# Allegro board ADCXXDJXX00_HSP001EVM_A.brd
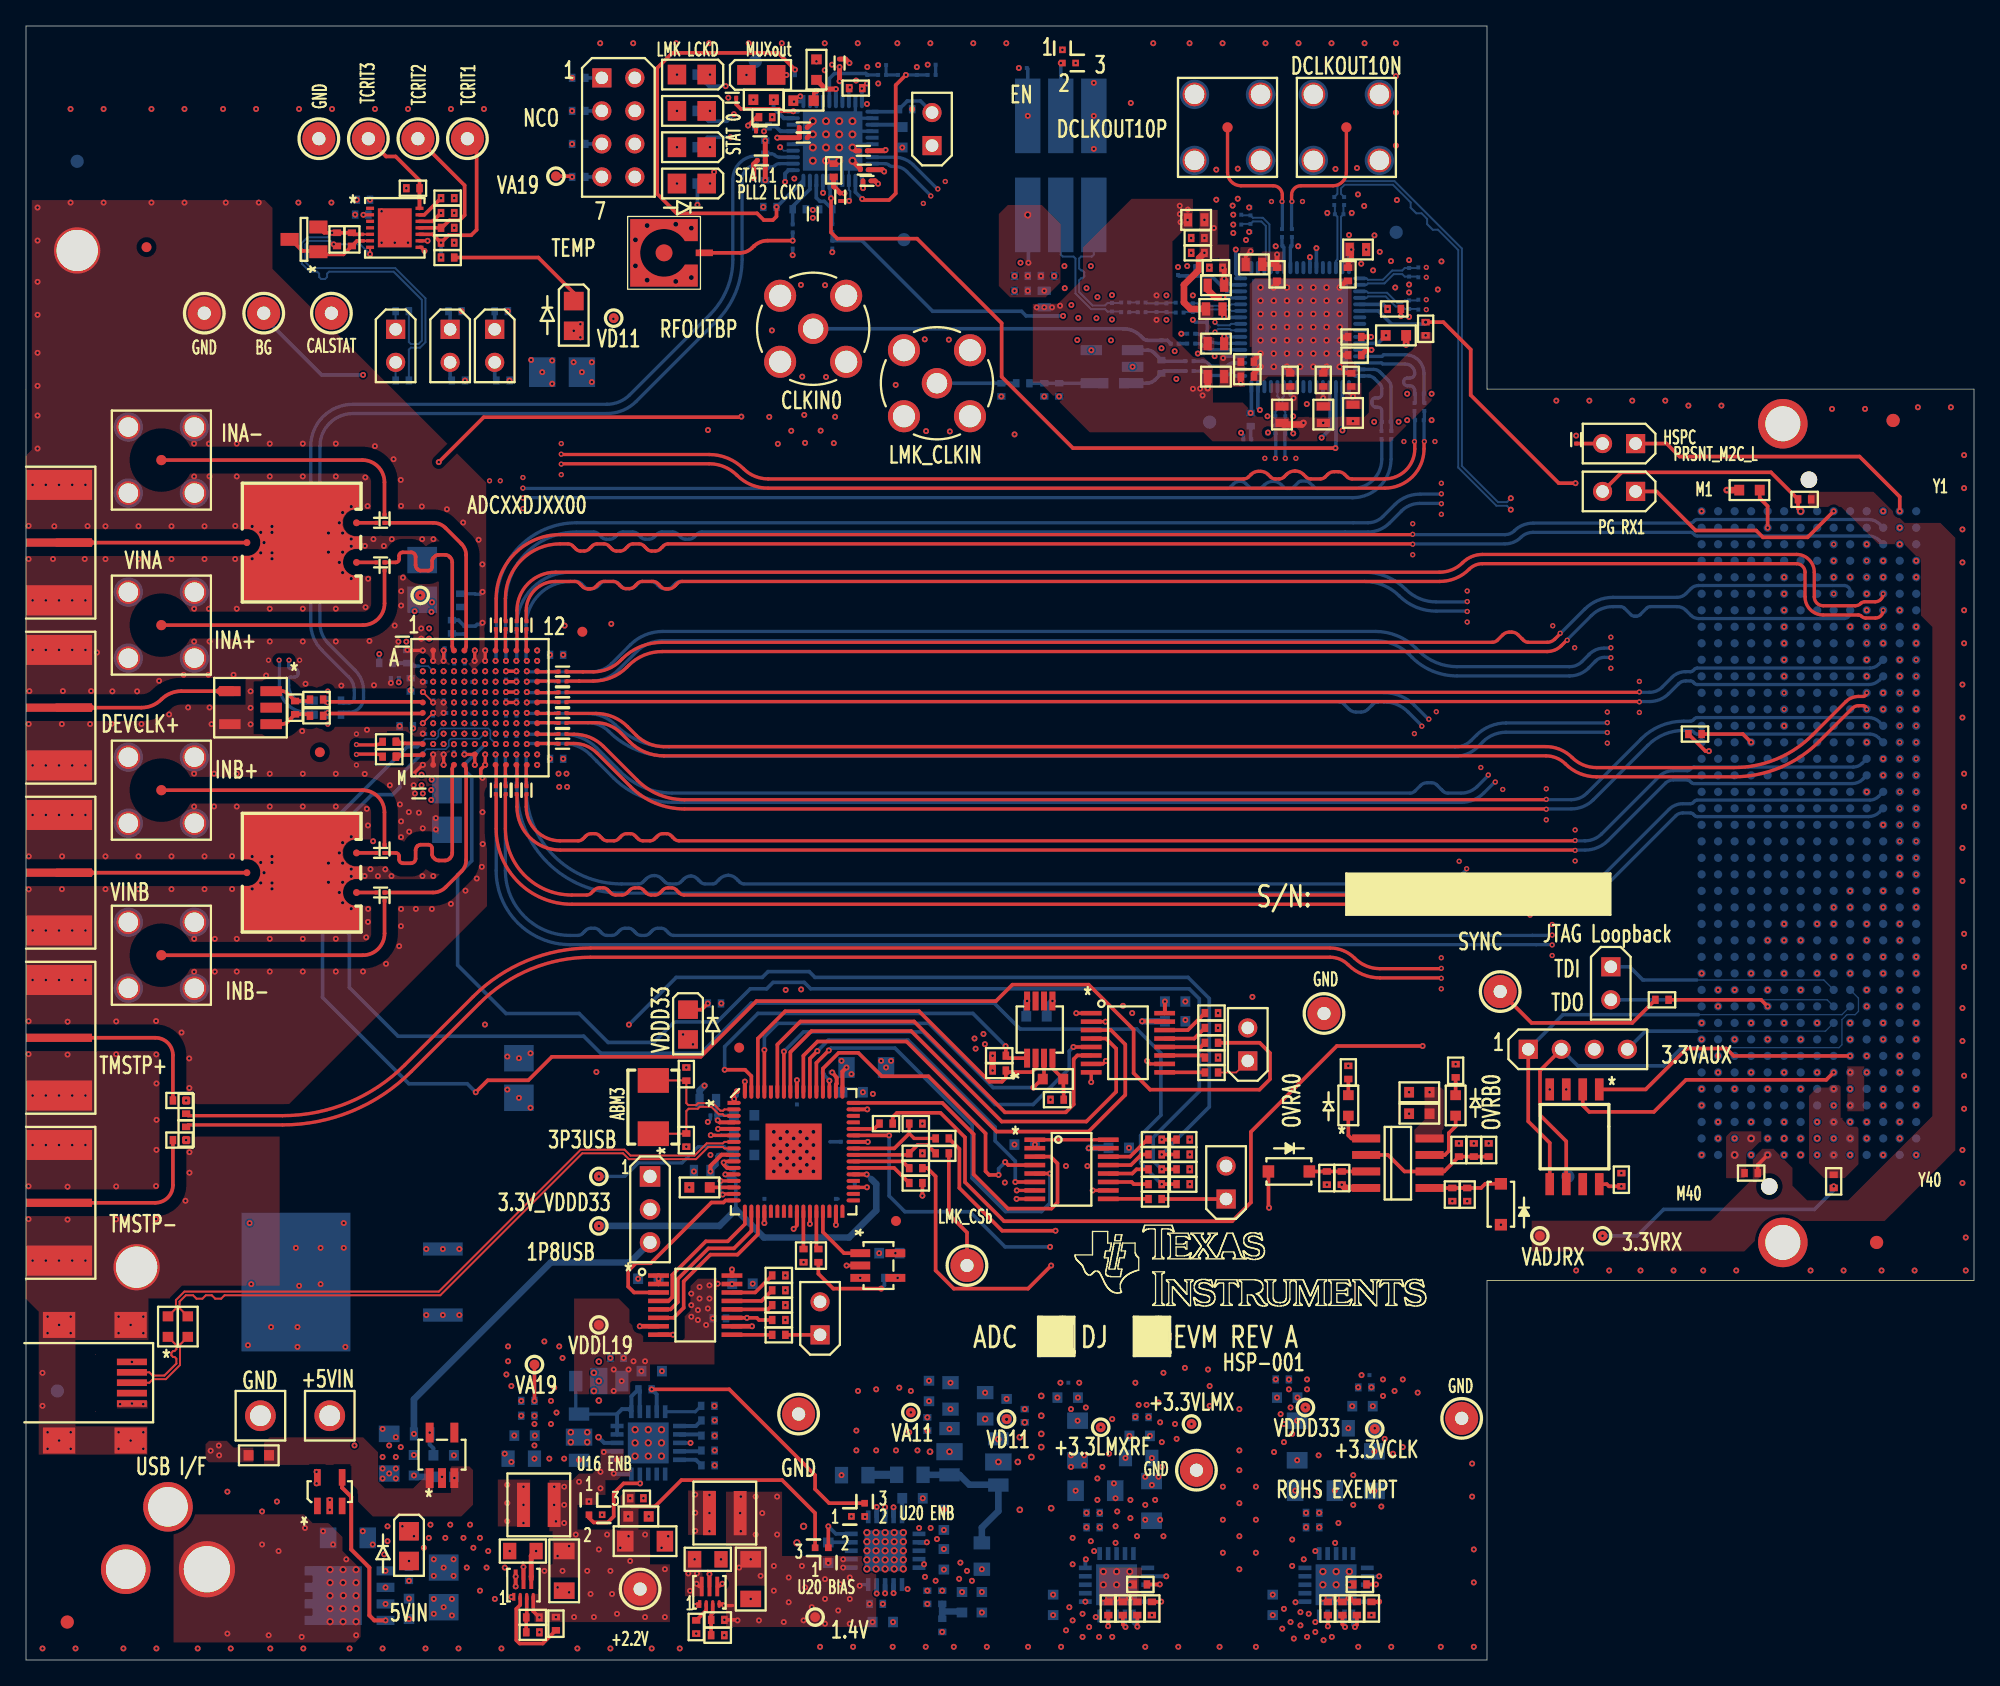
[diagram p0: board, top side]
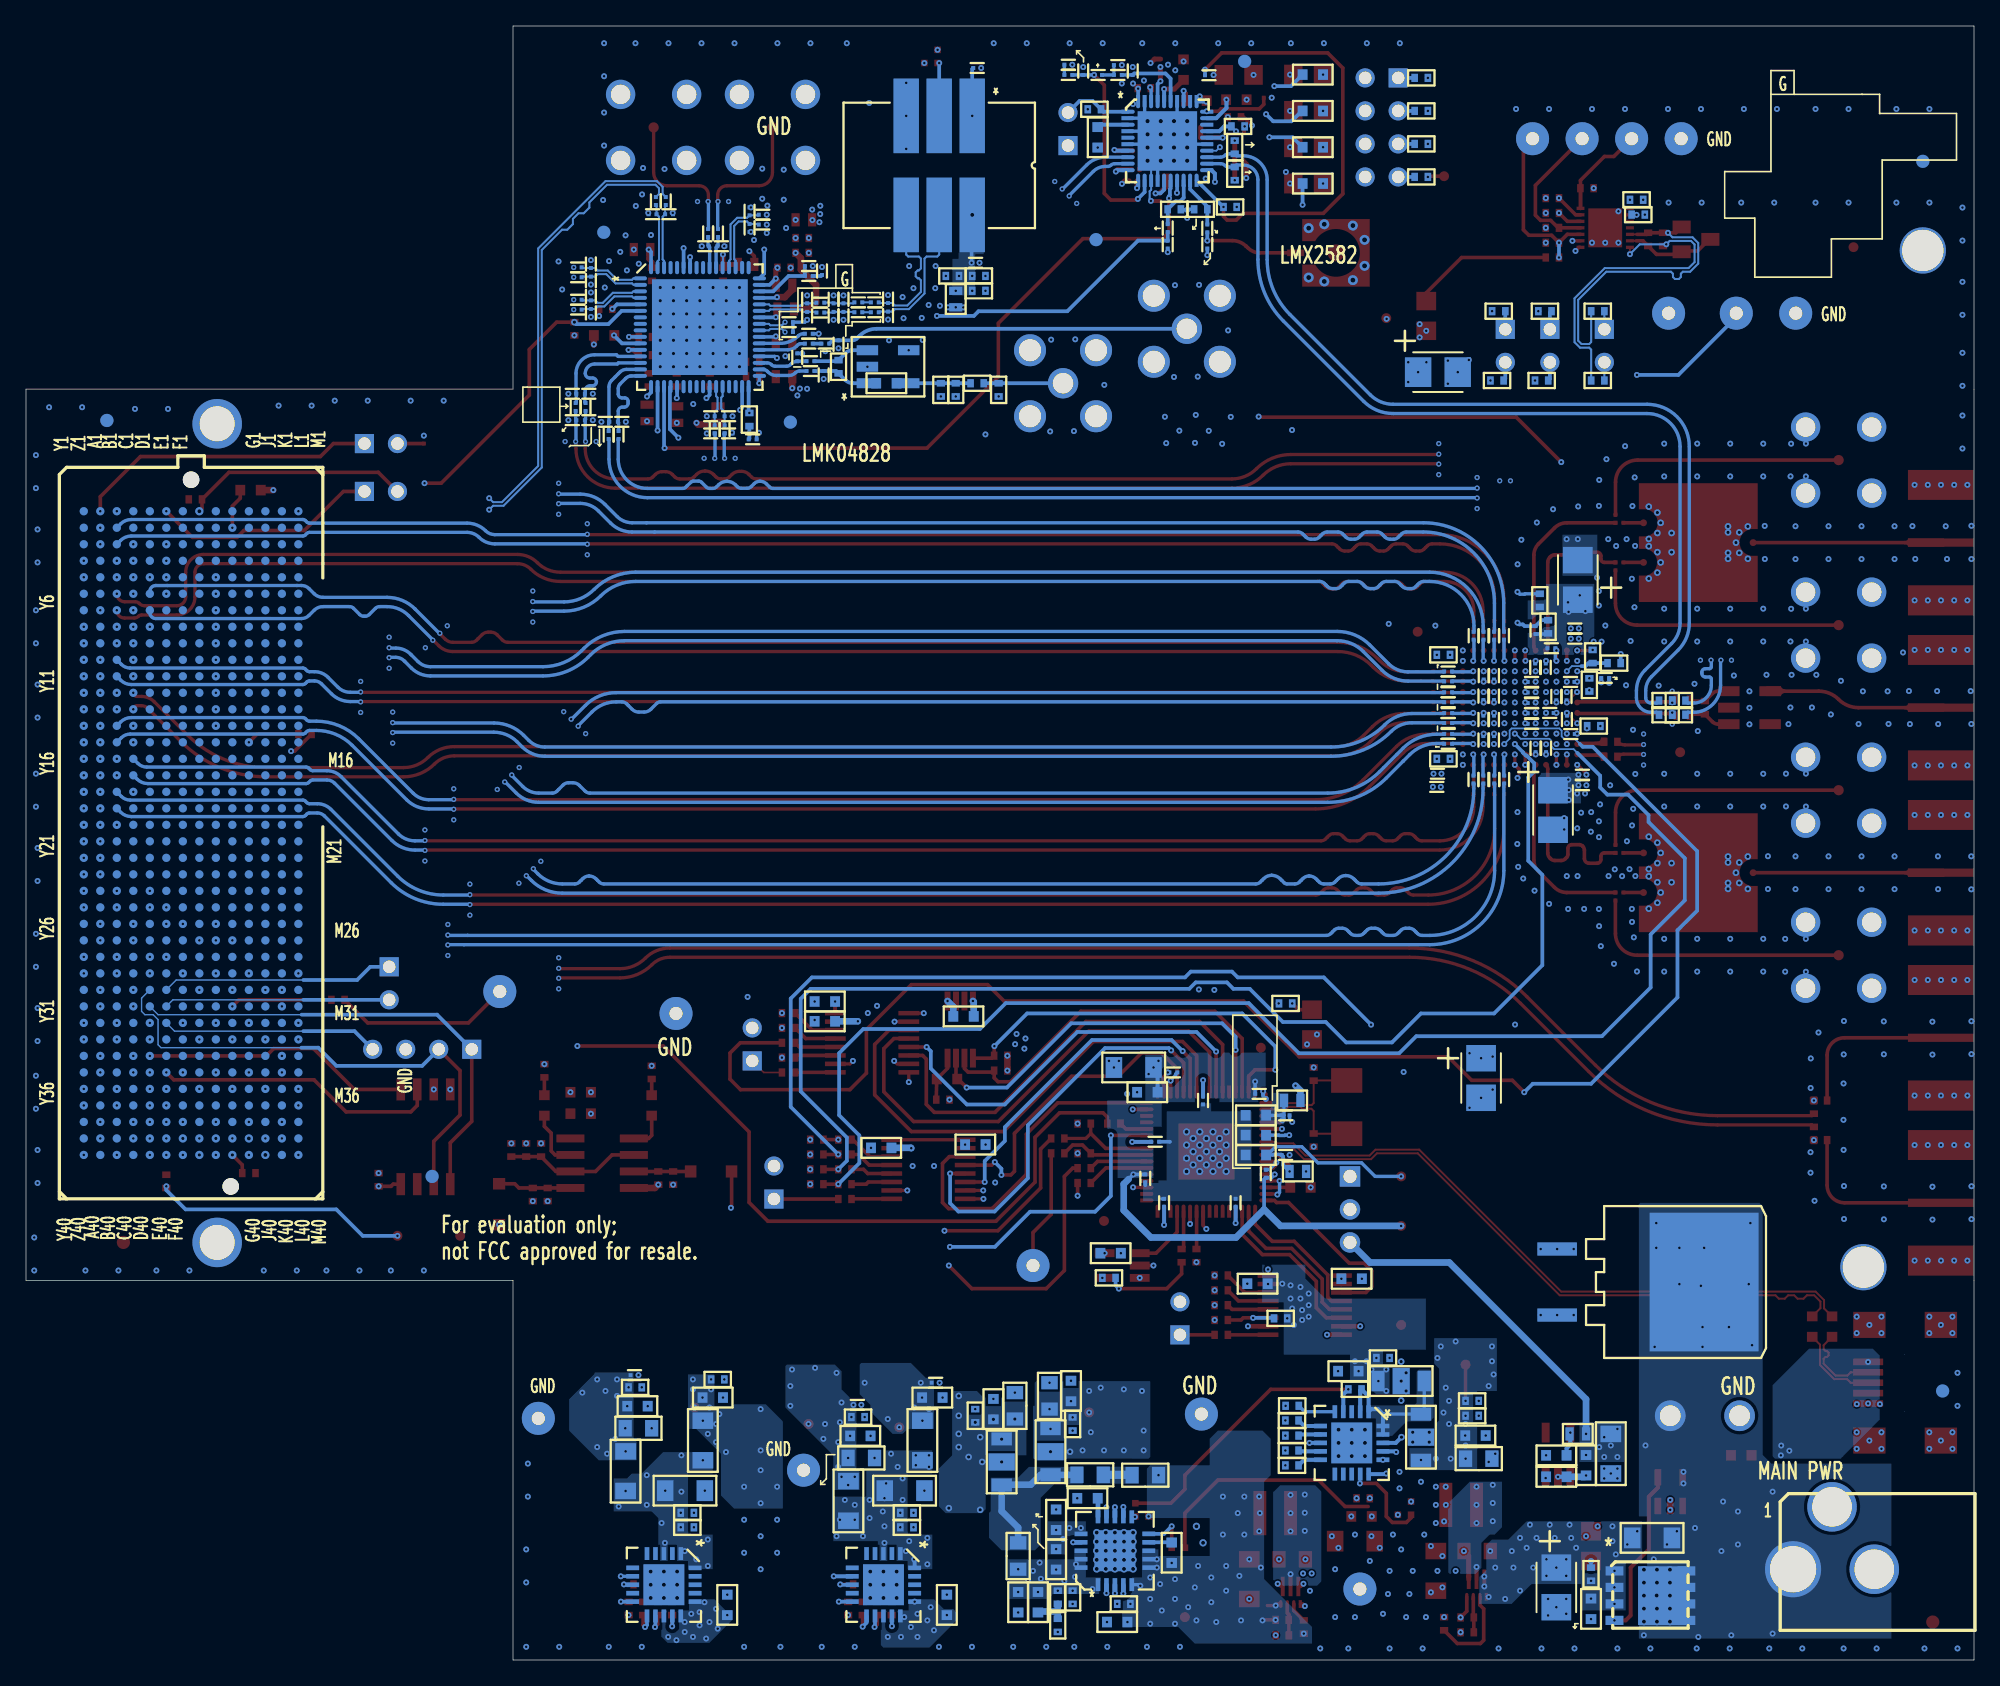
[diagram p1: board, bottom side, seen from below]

Outline 149.86 x 125.73 mm; copper layers: TOP, L02_GND-1, L03_GND-2, L04_SIG-1, L05_GND-3, L06_PWR-1, L07_GND-4, L08_PWR-2, L09_GND-5, L10_SIG-2, L11_GND-6, BOTTOM. Coordinates in mm from the lower left corner of the outline.
Outline path: 0,125.73 0,0 112.39,0 112.39,29.21 149.86,29.21 149.86,97.79 112.39,97.79 112.39,125.73 0,125.73

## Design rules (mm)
net group CLK: nets CLKM CLKP
net group CLKIN0_P_N: nets CLKIN0_N CLKIN0_P
net group CLKIN1: nets CLKIN1_N CLKIN1_P
net group CLKINN: nets CLKINN CLKINP
net group CLKLA0: nets CLKLA_0N CLKLA_0P
net group DA4: nets DA4+ DA4-
net group DA5: nets DA5+ DA5-
net group DA6: nets DA6+ DA6-
net group DA7: nets DA7+ DA7-
net group DB4: nets DB4+ DB4-
net group DB5: nets DB5+ DB5-
net group DB6: nets DB6+ DB6-
net group DB7: nets DB7+ DB7-
net group DCLKOUT2: nets DCLKOUT2_N DCLKOUT2_P
net group DCLKOUT8: nets DCLKOUT8_N DCLKOUT8_P
net group DCLKOUT102: nets DCLKOUT10_N DCLKOUT10_P
net group DIFFPAIR9: nets GTXCLKM GTXCLKP
net group DIFFPAIR10: nets N20382827 N20382847
net group DMP: nets DM DP
net group DP5: nets SYSREF+ SYSREF-
net group DP8: nets LMX_OSCM LMX_OSCP
net group DP17: nets JESD_SYSREFM JESD_SYSREFP
net group DP19: nets LMX_CLKM LMX_CLKP
net group FPGA_JESD_CLKC: nets FPGA_JESD_CLK_C_N FPGA_JESD_CLK_C_P
net group OSC: nets OSCN OSCP
net group OSC_PAIR: nets OSC_M OSC_P
net group OSCIN: nets OSCINN OSCINP
net group OSCIO: nets OSCI OSCO
net group OSCOUT: nets DCLKOUT6_N DCLKOUT6_P
net group SYNC: nets SYNC_N SYNC_P
net group SYSREF: nets SYSREFM SYSREFP
net group TDIODE: nets TDIODE+ TDIODE-
net group TDIODENP: nets TDIODEN TDIODEP
net group TMSTP: nets TMSTP+ TMSTP-
net group Y2: nets Y1_N Y1_P
net group YO1: nets YO1_N YO1_P
net group A-INPUT: nets CLK+ CLK- CLK_+ CLK_- DEVCLKIN INA+ INA- INA_+ INA_- INAN INAP INB+ INB- INB_+ INB_- INBN INBP TMSP+ TMSP- VINA VINB
net group HS: nets DA0+ DA0- DA0_M DA0_P DA1+ DA1- DA1_M DA1_P DA2+ DA2- DA2_M DA2_P DA3+ DA3- DA3_M DA3_P DA4_M DA4_P DA5_M DA5_P DA6_M DA6_P DA7_M DA7_P DB0+ DB0- DB0_M DB0_P DB1+ DB1- DB1_M DB1_P DB2+ DB2- DB2_M DB2_P DB3+ DB3- DB3_M DB3_P DB4_M DB4_P DB5_M DB5_P DB6_M DB6_P DB7_M DB7_P
net group LENGTH: nets FPGA_JESD_CLK_A_N FPGA_JESD_CLK_A_P FPGA_JESD_CLK_B_N FPGA_JESD_CLK_B_P FPGA_JESD_SYSREFM FPGA_JESD_SYSREFP

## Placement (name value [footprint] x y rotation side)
BALUN1  BALUN, HIGH POWER, SMT  [BALUN_320X320_MARKI_0006SMG]  21.21 85.98 90 top
BALUN2  BALUN, HIGH POWER, SMT  [BALUN_320X320_MARKI_0006SMG]  21.21 60.58 90 top
C1  0.1uF  [0603]  107.19 43.69 180 top
C2  1uF  [0603]  107.19 42.04 180 top
C3  .1uF  [0402]  101.22 37.08 90 top
C4  .1uF  [0402]  111.38 39.24 270 top
C5  .1uF  [0201]  41.27 74.46 0 top
C6  .1uF  [0201]  41.27 73.7 0 top
C7  .1uF  [0201]  41.27 76.06 0 top
C8  .1uF  [0201]  41.27 75.3 0 top
C9  .1uF  [0201]  37.74 79.63 90 top
C10  .1uF  [0201]  38.51 79.63 90 top
C11  .1uF  [0201]  36.14 79.63 90 top
C12  .1uF  [0201]  36.91 79.63 90 top
C13  .1uF  [0201]  40.46 74.46 0 bottom
C14  .1uF  [0402]  109.73 35.81 90 top
C15  .1uF  [0201]  40.46 73.7 0 bottom
C16  .1uF  [0201]  40.46 76.06 0 bottom
C18  .1uF  [0201]  40.46 75.3 0 bottom
C19  .1uF  [0201]  37.73 78.81 90 bottom
C20  .1uF  [0201]  89.64 101.29 0 bottom
C21  .1uF  [0201]  38.49 78.81 90 bottom
C22  .1uF  [0201]  36.16 78.81 90 bottom
C23  .1uF  [0201]  36.92 78.81 90 bottom
C24  .1uF  [0201]  89.64 102.05 0 bottom
C25  .1uF  [0201]  41.27 72.1 0 top
C26  .1uF  [0201]  41.27 72.86 0 top
C27  .1uF  [0201]  41.27 70.5 0 top
C28  .1uF  [0201]  41.27 71.26 0 top
C29  .1uF  [0201]  37.74 66.93 270 top
C30  .1uF  [0201]  38.51 66.93 270 top
C31  .1uF  [0201]  36.14 66.93 270 top
C32  .1uF  [0201]  36.91 66.93 270 top
C33  .1uF  [0201]  40.46 72.1 0 bottom
C34  .1uF  [0201]  40.46 72.86 0 bottom
C35  .1uF  [0201]  40.46 70.5 0 bottom
C36  .1uF  [0201]  40.46 71.26 0 bottom
C37  .1uF  [0201]  37.74 67.75 270 bottom
C38  .1uF  [0201]  38.51 67.75 270 bottom
C39  .1uF  [0201]  36.14 67.75 270 bottom
C40  .1uF  [0201]  36.91 67.75 270 bottom
C41  100pF  [0402]  25.83 111.22 180 bottom
C42  .1uF  [0402]  25.96 112.36 180 bottom
C43  10uF  [TANT_B]  41.24 99.09 180 bottom
C44  100pF  [0402]  23.93 109.31 90 top
C45  .1uF  [0402]  27.94 70.65 0 top
C46  100pF  [0402]  25.07 109.31 90 top
C47  .1uF  [0402]  27.94 69.51 0 top
C48  4700pF  [0402]  22.71 73.83 0 bottom
C49  4700pF  [0402]  22.35 73.91 0 top
C50  4700pF  [0402]  23.72 73.83 180 bottom
C51  4700pF  [0402]  23.72 72.73 180 bottom
C52  4700pF  [0402]  22.35 72.65 0 top
C53  4700pF  [0402]  22.71 72.73 0 bottom
C54  .1uF  [0201]  31.04 75.26 180 bottom
C55  .1uF  [0201]  33.76 76.38 90 bottom
C56  .1uF  [0201]  34.04 75.26 0 bottom
C57  .1uF  [0201]  31.01 71.25 180 bottom
C58  .1uF  [0201]  28.37 75.56 180 bottom
C59  .1uF  [0201]  33.73 70.15 270 bottom
C60  .1uF  [0201]  33.73 79.25 90 bottom
C61  .1uF  [0201]  32.51 77.85 180 bottom
C62  .1uF  [0201]  34.04 72.03 0 bottom
C63  .1uF  [0201]  34.04 72.85 0 bottom
C64  .1uF  [0201]  34.04 73.63 0 bottom
C65  .1uF  [0201]  34.04 74.45 0 bottom
C66  1uF  [0402]  32.77 79.5 90 bottom
C67  1uF  [0402]  33.4 81.53 90 bottom
C68  10uF  [TANT_B]  30.48 83.11 90 bottom
C69  .1uF  [0201]  32.94 76.38 90 bottom
C70  .1uF  [0201]  31.34 74.14 270 bottom
C71  .1uF  [0201]  32.13 74.14 270 bottom
C72  .1uF  [0201]  32.64 72.87 180 bottom
C73  .1uF  [0201]  31.32 72.36 90 bottom
C74  .1uF  [0201]  32.92 70.15 270 bottom
C75  .1uF  [0201]  30.71 78.59 180 bottom
C76  .1uF  [0201]  28.96 78.36 180 top
C77  .1uF  [0201]  30.23 66.67 180 top
C78  .1uF  [0201]  30.71 79.38 180 bottom
C79  .1uF  [0201]  30.12 68.12 180 bottom
C80  .1uF  [0201]  30.12 67.31 180 bottom
C81  1uF  [0402]  29.59 75.03 90 bottom
C82  1uF  [0402]  29.25 71.86 180 bottom
C83  10uF  [TANT_B]  32.39 65.41 270 bottom
C84  .1uF  [0201]  41.33 67.18 0 bottom
C85  .1uF  [0201]  37.74 70.79 90 bottom
C86  .1uF  [0201]  37.74 72.36 90 bottom
C87  .1uF  [0201]  36.93 72.36 90 bottom
C88  .1uF  [0201]  37.74 74.17 270 bottom
C89  .1uF  [0201]  36.93 74.17 270 bottom
C90  .1uF  [0201]  37.72 75.74 270 bottom
C91  .1uF  [0201]  36.93 75.74 270 bottom
C92  .1uF  [0201]  41.27 68.2 0 bottom
C93  1uF  [0402]  40.82 69.34 0 bottom
C94  1uF  [0402]  40.82 77.34 0 bottom
C95  10uF  [TANT_B]  37.92 44.78 270 bottom
C96  .1uF  [0201]  36.93 70.79 90 bottom
C99  100pF  [0201]  56.57 115.39 180 top
C100  .1uF  [0201]  64.42 116.12 180 top
C101  .1uF  [0201]  59.79 117.14 0 top
C102  1uF  [0402]  62.13 114.62 270 top
C103  .1uF  [0201]  64.7 113.81 0 top
C104  .1uF  [0201]  64.49 114.68 0 top
C105  100pF  [0201]  60.53 111.27 270 top
C106  .1uF  [0201]  62.64 112.57 270 top
C107  .1uF  [0201]  62.59 122.88 270 top
C108  100pF  [0201]  62.03 110.18 270 bottom
C109  .1uF  [0201]  56.47 117.62 180 top
C110  100pF  [0201]  58.98 110.15 270 bottom
C111  1uF  [0402]  56.62 118 0 bottom
C112  10uF  [0603]  56.75 120.06 0 top
C113  .1uF  [0201]  59.79 117.93 0 top
C114  1uF  [0402]  56.9 118.71 0 top
C115  10uF  [0603]  60.81 122.37 270 top
C116  10uF  [0603]  67.41 117.16 90 bottom
C117  1uF  [0402]  63.83 120.95 180 top
C118  10uF  [0603]  59.82 119.98 0 top
C119  560pF  [0201]  68.53 122.27 90 bottom
C120  .047uF  [0201]  69.67 121.96 0 bottom
C121  6800pF  [0201]  65.86 122.72 180 bottom
C122  6800pF  [0201]  64.72 122.27 90 bottom
C128  .68uF  [0402]  94.21 95.45 270 bottom
C130  .1uF  [0201]  76.68 122.5 180 bottom
C131  3900pF  [0201]  89.64 106.5 180 bottom
C132  47pF  [0201]  89.64 107.26 180 bottom
C133  .1uF  [0201]  105.04 94.26 270 bottom
C134  .01uF  [0201]  89.51 99.18 0 bottom
C135  .1uF  [0201]  104.27 94.26 270 bottom
C136  .01uF  [0201]  89.51 99.94 0 bottom
C137  .1uF  [0201]  90.53 100.24 270 bottom
C138  .1uF  [0201]  76.81 107.51 0 bottom
C139  100pF  [0402]  76.56 106.5 0 bottom
C140  2200pF  [0402]  78.59 106.5 180 bottom
C141  10pF  [0402]  76.56 105.35 0 bottom
C142  .1uF  [0201]  96.62 109.8 90 bottom
C143  .1uF  [0201]  97.39 109.8 90 bottom
C144  .1uF  [0201]  85.83 103.7 0 bottom
C145  .1uF  [0201]  88.75 103.68 0 bottom
C146  .1uF  [0201]  89.77 103.43 90 bottom
C149  .1uF  [0201]  85.83 104.46 0 bottom
C150  .1uF  [0201]  88.75 104.44 0 bottom
C151  .1uF  [0201]  96.88 94.69 270 bottom
C152  12pF  [0201]  89.77 104.7 270 bottom
C153  .1uF  [0201]  96.12 94.69 270 bottom
C154  1uF  [0402]  102.21 101.8 0 top
C155  .1uF  [0402]  93.96 98.75 180 top
C156  0.01uF  [0402]  93.96 99.89 180 top
C157  1uF  [0402]  101.96 98.5 90 top
C158  1uF  [0402]  99.8 98.5 90 top
C159  1uF  [0402]  97.26 98.5 90 top
C160  1uF  [0402]  90.15 109.42 0 top
C161  .1uF  [0402]  90.15 108.27 0 top
C162  0.01uF  [0402]  91.54 107.13 0 top
C163  .1uF  [0402]  102.21 100.4 180 top
C164  10uF  [0603]  105.39 101.92 0 top
C165  1uF  [0402]  96.24 106.62 270 top
C166  1uF  [0402]  101.7 106.62 270 top
C167  1uF  [0402]  122.73 36.96 270 top
C168  10uF  [0603]  55.24 41.91 0 bottom
C169  .1uF  [0201]  52.96 41.91 180 bottom
C170  10uF  [0603]  55.24 38.86 0 bottom
C171  .1uF  [0201]  52.96 38.86 180 bottom
C172  0.1uF  [0603]  66.42 31.3 180 bottom
C173  1uF  [0603]  32.13 15.75 0 bottom
C174  100uF  [1206]  27.94 15.87 270 bottom
C175  1uF  [0603]  32.13 14.1 180 bottom
C176  .1uF  [0201]  61.59 45.21 180 bottom
C177  0.1uF  [0603]  29.84 14.99 270 bottom
C178  100uF  [1206]  64.64 45.59 0 bottom
C179  10uF  [0603]  63.6 43.69 0 bottom
C180  1uF  [0603]  77.74 49.53 0 bottom
C181  .1uF  [0201]  54.99 43.56 180 bottom
C182  .1uF  [0201]  54.48 37.42 90 bottom
C183  .1uF  [0201]  63.75 37.06 270 bottom
C184  18pF  [0402]  50.8 45.09 90 top
C185  18pF  [0402]  50.8 40 270 top
C186  .1uF  [0201]  56.8 35.18 90 bottom
C187  .1uF  [0201]  62.99 39.88 180 bottom
C188  .1uF  [0201]  62.31 35.18 90 bottom
C189  .1uF  [0201]  59.31 43.05 270 bottom
C190  0.1uF  [0603]  47.88 29.34 180 bottom
C191  0.1uF  [0603]  55.12 28.96 0 bottom
C192  0.1uF  [0603]  76.83 39.66 180 bottom
C193  0.1uF  [0603]  84.07 39.41 0 bottom
C194  0.1uF  [0603]  88.4 50.67 0 bottom
C195  0.1uF  [0603]  88.4 49.14 0 bottom
C196  47uF  [TANT_B]  32.13 5.59 270 bottom
C198  10uF  [0603]  29.46 3.94 270 bottom
C200  10uF  [0603]  48.13 22.23 0 bottom
C201  1uF  [0402]  45.47 23.24 180 bottom
C202  10uF  [0603]  38.35 17.27 180 bottom
C203  .1uF  [0402]  38.61 19.94 180 bottom
C204  33uF  [0805]  38.1 15.49 180 bottom
C205  1uF  [0402]  38.61 18.8 180 bottom
C206  22uF  [1206]  41.4 6.86 270 top
C207  47uF  [1206]  47.62 9.14 0 top
C208  10uF  [0603]  47.12 11.05 0 top
C209  10uF  [0805]  38.23 8.38 0 top
C210  1uF  [0402]  46.99 12.45 0 top
C211  22uF  [1206]  55.75 6.22 270 top
C212  2.2uF  [0603]  65.91 2.92 0 bottom
C213  1uF  [0402]  65.41 4.32 0 bottom
C214  1uF  [0402]  69.34 4.83 270 bottom
C215  10uF  [0805]  52.45 7.75 0 top
C216  .47uF  [0603]  72.01 4.45 270 bottom
C217  10uF  [0603]  73.53 4.45 270 bottom
C218  33uF  [0805]  71.12 20.32 90 bottom
C219  10uF  [0603]  69.47 20.7 90 bottom
C220  1uF  [0402]  69.34 18.16 270 bottom
C221  1000pF  [0603]  68.2 12.45 0 bottom
C222  33uF  [0805]  73.79 19.56 90 bottom
C223  10uF  [0603]  75.44 19.3 90 bottom
C224  1uF  [0402]  76.83 18.8 90 bottom
C225  10uF  [0603]  95.91 4.24 90 bottom
C226  .1uF  [0402]  98.98 11.33 180 bottom
C227  1uF  [0402]  98.98 10.21 180 bottom
C228  47uF  [1206]  99.16 13.03 180 bottom
C229  33uF  [0805]  102.74 17.83 180 bottom
C230  10uF  [0603]  102.82 19.53 180 bottom
C233  .1uF  [0402]  103 20.98 180 bottom
C234  .01uF  [0201]  103.05 21.92 180 bottom
C235  1uF  [0402]  100.15 3.96 90 top
C236  10uF  [0603]  97.03 20.19 180 bottom
C237  .1uF  [0402]  96.65 21.59 180 bottom
C238  10uF  [0603]  79.02 4.24 90 bottom
C239  .1uF  [0402]  82.09 10.21 180 bottom
C240  1uF  [0402]  82.09 11.33 180 bottom
C241  47uF  [1206]  82.27 13.03 180 bottom
C242  33uF  [0805]  85.6 15.54 180 bottom
C243  10uF  [0603]  85.67 17.25 180 bottom
C244  .1uF  [0402]  85.85 18.69 180 bottom
C245  .01uF  [0201]  85.9 19.63 180 bottom
C246  1uF  [0402]  83.26 3.96 90 top
C247  10uF  [0603]  80.14 20.19 180 bottom
C248  .01uF  [0201]  79.88 21.34 180 bottom
C249  .1uF  [0201]  97.18 94.38 0 bottom
C250  .1uF  [0201]  95.81 94.38 180 bottom
D1  LED RED  [LED_0805]  42.14 103.42 90 top
D2  LED GREEN  [LED_0805]  56.57 121.97 180 top
D3  LED GREEN  [LED_0805]  51.22 119.2 0 top
D4  LED GREEN  [LED_0805]  51.22 116.4 0 top
D5  LED GREEN  [LED_0805]  51.22 121.99 0 top
D6  LED GREEN  [LED_0805]  51.22 113.61 0 top
D7  LED GREEN  [LED_0805]  50.93 48.89 90 top
D8  LED GREEN  [LED_0805]  29.46 8.76 90 top
D9  1N4148W  [DIODE_SM_1N4148W]  113.46 35.07 90 top
D10  LED ORANGE  [LED_0603]  109.98 42.67 90 top
D11  LED ORANGE  [LED_0603]  101.73 42.67 90 top
D12  1N4148W  [DIODE_SM_1N4148W]  97.16 37.59 0 top
D13  MBRB2515L  [DIODE_MBRB2515L]  26.42 29.08 0 bottom
F1  FUSE 10A 63V FAST  [1206]  24.77 9.4 0 bottom
FB1  120 OHM @ 100MHz  [IND_0603]  78.34 104.72 270 bottom
FB2  120 OHM @ 100MHz  [IND_0603]  91.54 98.75 0 top
FB3  120 OHM @ 100MHz  [IND_0603]  102.08 95.96 90 top
FB4  120 OHM @ 100MHz  [IND_0603]  99.8 95.83 90 top
FB5  120 OHM @ 100MHz  [IND_0603]  96.62 95.83 90 top
FB6  120 OHM @ 100MHz  [IND_0603]  90.02 110.81 0 top
FB7  120 OHM @ 100MHz  [IND_0603]  91.54 101.29 0 top
FB8  120 OHM @ 100MHz  [IND_0603]  91.42 103.96 0 top
FB9  120 OHM @ 100MHz  [IND_0603]  91.54 105.79 180 top
FB10  120 OHM @ 100MHz  [IND_0603]  94.46 107.39 0 top
FB11  120 OHM @ 100MHz  [IND_0603]  102.47 108.53 180 top
FB12  120 OHM @ 100MHz  [IND_0603]  52.45 43.05 0 bottom
FB13  120 OHM @ 100MHz  [IND_0603]  52.02 37.59 0 bottom
FB14  26 OHM @ 100MHz  [IND_0603]  30.48 17.4 180 bottom
FB16  27uF  [1206_BEAD_NFM31P]  44.07 21.46 0 bottom
FB17  27uF  [1206_BEAD_NFM31P]  42.55 17.14 270 bottom
FB18  27uF  [1206_BEAD_NFM31P]  71.04 16.03 90 bottom
FB19  27uF  [1206_BEAD_NFM31P]  74.8 15.24 90 bottom
FB20  120 OHM @ 100MHz  [1206]  103.73 14.53 90 bottom
FB21  120 OHM @ 100MHz  [1206]  97.79 16.89 90 bottom
FB22  120 OHM @ 100MHz  [1206]  86.59 12.24 90 bottom
FB23  120 OHM @ 100MHz  [1206]  80.9 16.89 90 bottom
J1  SMA, THVT, SMT CENTER PIN  [SMA_THVT_SMT_250X250]  10.41 79.63 0 top
J2  SMA, JACK, 50 OHM, EDGE MNT  [SMA_SMEL_373X312]  0 85.98 90 top
J3  SMA, THVT, SMT CENTER PIN  [SMA_THVT_SMT_250X250]  10.41 92.33 0 top
J4  SMA, THVT, SMT CENTER PIN  [SMA_THVT_SMT_250X250]  10.41 66.93 0 top
J5  SMA, JACK, 50 OHM, EDGE MNT  [SMA_SMEL_373X312]  0 60.58 90 top
J6  SMA, THVT, SMT CENTER PIN  [SMA_THVT_SMT_250X250]  10.41 54.23 0 top
J7  HDR, THVT, 8POS, .100, GOLD  [HDR_THVT_2X4_100_M]  44.3 121.74 0 top
J8  HDR, THVT, 2POS, .100, GOLD  [HDR_THVT_1X2_100_M]  32.63 102.39 0 top
J9  HDR, THVT, 2POS, .100, GOLD  [HDR_THVT_1X2_100_M]  36.06 102.39 0 top
J14  SMA, JACK, 50 OHM, EDGE MNT  [SMA_SMEL_373X312]  0 47.88 90 top
J15  SMA, JACK, 50 OHM, EDGE MNT  [SMA_SMEL_373X312]  0 35.18 90 top
J17  HDR, THVT, 2POS, .100, GOLD  [HDR_THVT_1X2_100_M]  28.44 102.39 0 top
J18  SMA, JACK, 50 OHM, EDGE MNT  [SMA_SMEL_373X312]  0 73.28 90 top
J20  SMP, PCB, SMT  [SMP_B120]  49.08 108.27 90 top
J22  SMA_THVT_REC  [SMA_THVT_312X312]  70.08 98.24 0 top
J23  SMA, THVT, SMT CENTER PIN  [SMA_THVT_SMT_250X250]  92.43 117.93 0 top
J24  SMA, THVT, SMT CENTER PIN  [SMA_THVT_SMT_250X250]  101.58 117.93 0 top
J25  CON, SMVT, HS, FIELD ARRAY, FMC, MALE  [CON_SMVT_40X14_50_M_MTG]  137.16 63.63 90 bottom
J26  HDR, THVT, 2POS, .100, GOLD  [HDR_THVT_1X2_100_M]  123.83 89.92 270 top
J27  HDR, THVT, 2POS, .100, GOLD  [HDR_THVT_1X2_100_M]  121.92 53.34 0 top
J28  HDR, THVT, 4POS, .100, GOLD  [HDR_THVT_1X4_100_M]  115.57 46.99 90 top
J30  HDR, THVT, 2POS, .100, GOLD  [HDR_THVT_1X2_100_M]  123.83 93.6 270 top
J31  CON, USB, MINI, AB, SMT  [CON_SMRT_USBMNE20_F]  4.7 21.34 0 top
J37  CONN, JACK, PWR, MINI, R/A, TH  [CON_RAPC722_JACK_THVT_3]  10.79 6.98 90 bottom
J38  SMA_THVT_REC  [SMA_THVT_312X312]  60.56 102.43 0 top
JP5  HDR, THVT, 2POS, .100, GOLD  [HDR_THVT_1X2_100_M]  69.7 116.53 180 top
JP6  HDR, THVT, 3POS, .100, GOLD  [HDR_THVT_1X3_100_M]  48.01 37.21 0 top
JP7  HDR, THVT, 2POS, .100, GOLD  [HDR_THVT_1X2_100_M]  61.09 25.02 180 top
JP8  HDR, THVT, 2POS, .100, GOLD  [HDR_THVT_1X2_100_M]  92.32 35.47 180 top
JP9  HDR, THVT, 2POS, .100, GOLD  [HDR_THVT_1X2_100_M]  93.99 46.1 180 top
L3  .47uH  [IND_SM_XFL4015]  39.45 11.94 0 top
L4  .47uH  [IND_SM_XFL4015]  53.76 11.3 0 top
MT1  STANDOFF, FEMALE, 4-40 X 1 3/16", AL  [MFG125_PLATED]  3.94 108.46 0 top
MT2  STANDOFF, FEMALE, 4-40 X 1 3/16", AL  [MFG125_PLATED]  8.51 30.23 0 top
NOREF  -  []  145.42 61.72 0 top
NOREF#2  -  []  38.52 71.28 0 top
NOREF#3  -  []  38.52 73.68 0 top
NOREF#4  -  []  32.93 68.88 0 top
NOREF#5  -  []  112.76 67.83 135 top
NOREF#6  -  []  19.85 76.93 180 top
NOREF#7  -  []  142.88 82.04 0 top
NOREF#8  -  []  70.08 98.24 0 top
NOREF#9  -  []  36.92 69.68 0 top
NOREF#10  -  []  144.14 68.07 0 top
NOREF#11  -  []  39.33 71.28 270 top
NOREF#12  -  []  41.27 76.06 180 top
NOREF#13  -  []  30.52 73.68 270 top
NOREF#14  -  []  21.46 72.21 0 top
NOREF#15  -  []  27.28 62.1 0 top
NOREF#16  -  []  115.71 58.51 90 top
NOREF#17  -  []  37.73 77.68 0 top
NOREF#18  -  []  2.54 47.88 0 top
NOREF#19  -  [unnamed#2]  142.37 32.13 0 top
NOREF#20  -  [unnamed#2]  3.18 2.92 0 top
NOREF#21  -  []  38.52 68.88 180 top
NOREF#22  -  []  144.14 74.42 0 top
NOREF#23  -  []  23.22 73.28 90 top
NOREF#24  -  []  25.43 87.5 0 top
NOREF#25  -  []  101.58 117.93 0 top
NOREF#26  -  []  108.88 89.35 90 top
NOREF#27  -  []  27.28 84.45 0 top
NOREF#28  -  []  141.61 79.5 0 top
NOREF#29  -  []  36.92 76.88 0 top
NOREF#30  -  []  25.42 70.06 90 top
NOREF#31  -  [unnamed#3]  66.93 33.78 0 top
NOREF#32  -  []  144.14 73.15 0 top
NOREF#33  -  []  39.33 74.48 270 top
NOREF#34  -  []  2.54 85.98 0 top
NOREF#35  -  []  41.27 70.5 180 top
NOREF#36  -  []  41.18 92.4 90 top
NOREF#37  -  []  38.52 72.08 0 top
NOREF#38  -  []  116.96 65.84 90 top
NOREF#39  -  []  36.12 76.88 0 top
NOREF#40  -  []  36.12 69.68 0 top
NOREF#41  -  []  18.86 72.01 0 top
NOREF#42  -  []  69.88 112.92 45 top
NOREF#43  -  [unnamed#3]  42.8 79.12 0 top
NOREF#44  -  []  141.61 74.42 0 top
NOREF#45  -  []  39.33 76.08 270 top
NOREF#46  -  []  124.12 74.1 90 top
NOREF#47  -  []  142.88 80.77 0 top
NOREF#48  -  []  141.61 73.15 0 top
NOREF#49  -  []  142.88 76.96 270 top
NOREF#50  -  []  27.28 59.05 0 top
NOREF#51  -  []  0 0 90 top
NOREF#52  -  []  36.12 77.68 0 top
NOREF#53  -  []  16.99 85.98 0 top
NOREF#54  -  []  112.39 0 90 top
NOREF#55  -  []  38.52 74.48 0 top
NOREF#56  -  []  -110.52 -120.02 0 top
NOREF#57  -  []  18.86 74.55 0 top
NOREF#58  -  []  36.91 79.63 90 top
NOREF#59  -  []  2.54 35.18 0 top
NOREF#60  -  []  60.56 102.43 0 top
NOREF#61  -  []  27.58 84.15 90 top
NOREF#62  -  [unnamed#3]  9.27 108.71 0 top
NOREF#63  -  []  41.27 71.26 180 top
NOREF#64  -  []  119.17 62.68 90 top
NOREF#65  -  []  25.43 84.45 0 top
NOREF#66  -  []  121.65 71.75 90 top
NOREF#67  -  []  78.16 23.95 0 top
NOREF#68  -  []  25.43 59.05 0 top
NOREF#69  -  []  94.58 57.98 0 top
NOREF#70  -  []  38.51 79.63 90 top
NOREF#71  -  []  145.42 70.61 0 top
NOREF#72  -  []  38.51 66.93 90 top
NOREF#73  -  []  118.29 78.73 135 top
NOREF#74  -  []  25.43 62.1 0 top
NOREF#75  -  []  110.87 81.06 90 top
NOREF#76  -  []  41.27 72.1 180 top
NOREF#77  -  []  238.12 40.64 0 top
NOREF#78  -  []  38.52 72.88 0 top
NOREF#79  -  []  142.88 87.12 270 top
NOREF#80  -  []  16.99 60.58 0 top
NOREF#81  -  []  38.23 89.79 90 top
NOREF#82  -  []  117.41 55.4 90 top
NOREF#83  -  []  141.61 83.31 0 top
NOREF#84  -  []  38.52 70.48 0 top
NOREF#85  -  []  142.88 71.88 270 top
NOREF#86  -  []  10.41 79.63 0 top
NOREF#87  -  []  70.8 23.95 0 top
NOREF#88  -  []  36.14 79.63 90 top
NOREF#89  -  []  140.33 82.04 270 top
NOREF#90  -  []  122.17 58.8 0 top
NOREF#91  -  []  2.54 73.28 0 top
NOREF#92  -  []  27.58 58.75 90 top
NOREF#93  -  []  0 0 0 top
NOREF#94  -  []  141.61 69.34 270 top
NOREF#95  -  []  92.43 117.93 0 top
NOREF#96  -  []  106.68 86.24 90 top
NOREF#97  -  []  15.68 74.55 180 top
NOREF#98  -  []  22.45 96.53 0 top
NOREF#99  -  []  0 125.73 0 top
NOREF#100  -  []  112.39 97.79 90 top
NOREF#101  -  []  107.19 93.76 0 top
NOREF#102  -  [unnamed#2]  143.64 95.38 0 top
NOREF#103  -  []  141.61 78.23 0 top
NOREF#104  -  []  145.42 66.8 0 top
NOREF#105  -  []  41.27 72.86 180 top
NOREF#106  -  []  144.14 69.34 0 top
NOREF#107  -  [unnamed#3]  22.61 69.85 0 top
NOREF#108  -  []  145.42 60.45 0 top
NOREF#109  -  []  10.41 92.33 0 top
NOREF#110  -  []  111.1 60.61 135 top
NOREF#111  -  []  41.27 73.7 180 top
NOREF#112  -  []  38.52 75.28 0 top
NOREF#113  -  []  145.42 65.53 0 top
NOREF#114  -  []  107.65 72.12 45 top
NOREF#115  -  []  141.61 84.58 0 top
NOREF#116  -  []  36.14 66.93 90 top
NOREF#117  -  []  36.91 66.93 90 top
NOREF#118  -  []  37.74 66.93 90 top
NOREF#119  -  []  -99.82 354.48 0 top
NOREF#120  -  []  145.42 76.96 0 top
NOREF#121  -  []  39.33 72.88 270 top
NOREF#122  -  []  27.58 62.41 90 top
NOREF#123  -  []  27.28 87.5 0 top
NOREF#124  -  []  37.73 69.68 0 top
NOREF#125  -  []  10.41 54.23 0 top
NOREF#126  -  []  38.52 76.08 0 top
NOREF#127  -  []  41.27 74.46 180 top
NOREF#128  -  []  145.42 75.69 0 top
NOREF#129  -  []  37.73 76.88 0 top
NOREF#130  -  [unnamed#3]  54.86 47.12 0 top
NOREF#131  -  []  36.92 68.88 180 top
NOREF#132  -  []  10.41 66.93 0 top
NOREF#133  -  []  92.96 76.58 0 top
NOREF#134  -  []  97.01 112.23 180 top
NOREF#135  -  []  32.93 77.68 0 top
NOREF#136  -  []  142.88 66.8 270 top
NOREF#137  -  []  96.5 92.46 0 top
NOREF#138  -  []  108.88 52.84 90 top
NOREF#139  -  []  38.52 69.68 0 top
NOREF#140  -  []  37.74 79.63 90 top
NOREF#141  -  []  38.52 76.88 0 top
NOREF#142  -  []  2.54 60.58 0 top
NOREF#143  -  []  30.52 70.48 270 top
NOREF#144  -  []  149.86 29.21 90 top
NOREF#145  -  []  121.92 77.51 90 top
NOREF#146  -  []  145.42 71.88 0 top
NOREF#147  -  []  41.27 75.3 180 top
NOREF#148  -  []  27.58 87.81 90 top
NOREF#149  -  [unnamed#2]  3.94 115.32 180 bottom
NOREF#150  -  []  36.91 67.75 90 bottom
NOREF#151  -  []  40.46 74.46 180 bottom
NOREF#152  -  []  40.46 73.7 180 bottom
NOREF#153  -  []  104.27 94.26 90 bottom
NOREF#154  -  []  211.59 35.07 180 bottom
NOREF#155  -  []  40.46 75.3 180 bottom
NOREF#156  -  []  104.02 95.27 180 bottom
NOREF#157  -  []  105.29 95.27 180 bottom
NOREF#158  -  []  40.46 70.5 180 bottom
NOREF#159  -  [unnamed#2]  118.62 37.21 180 bottom
NOREF#160  -  []  40.46 72.1 180 bottom
NOREF#161  -  [unnamed#2]  105.41 109.86 180 bottom
NOREF#162  -  [unnamed#2]  67.54 109.29 180 bottom
NOREF#163  -  []  36.14 67.75 90 bottom
NOREF#164  -  []  38.51 67.75 90 bottom
NOREF#165  -  []  36.16 78.81 90 bottom
NOREF#166  -  []  105.04 94.26 90 bottom
NOREF#167  -  [unnamed#2]  56.11 123.01 180 bottom
NOREF#168  -  [unnamed#2]  143.64 95.38 180 bottom
NOREF#169  -  []  40.46 72.86 180 bottom
NOREF#170  -  []  38.49 78.81 90 bottom
NOREF#171  -  []  40.46 71.26 180 bottom
NOREF#172  -  []  40.46 76.06 180 bottom
NOREF#173  -  []  37.74 67.75 90 bottom
NOREF#174  -  [unnamed#2]  91.06 95.25 180 bottom
NOREF#175  -  []  36.92 78.81 90 bottom
NOREF#176  -  [unnamed#2]  2.41 20.7 180 bottom
NOREF#177  -  []  37.73 78.81 90 bottom
Q1  NPN, MMBT3904  [SOT_23_MMBT3904]  21.39 109.31 90 top
Q3  CSD18532Q5  [SON_Q5B_8]  24.89 4.95 180 bottom
R1  0  [0201]  27.28 84.45 0 top
R4  0  [0201]  27.28 87.5 0 top
R6  0  [0201]  27.28 62.1 0 top
R9  0  [0201]  27.28 59.05 0 top
R11  10k  [0402]  89.02 40.04 0 top
R12  10k  [0402]  89.02 38.9 0 top
R13  1k  [0402]  42.52 121.74 0 bottom
R14  1k  [0402]  42.52 119.2 0 bottom
R15  1k  [0402]  42.52 116.66 0 bottom
R16  1k  [0402]  42.52 114.12 0 bottom
R17  10k  [0402]  89.02 37.76 0 top
R18  10k  [0402]  89.02 36.61 0 top
R19  1k  [0402]  33.01 103.79 180 bottom
R20  1k  [0402]  36.56 103.79 180 bottom
R21  10k  [0402]  33.26 98.45 0 bottom
R22  0  [0201]  93.18 110.45 180 bottom
R23  10k  [0402]  36.69 98.45 0 bottom
R24  0  [0201]  93.18 111.21 180 bottom
R25  1k  [0402]  27.69 76.71 0 bottom
R26  2.1k  [0402]  29.34 77.22 90 bottom
R27  10k  [0402]  32.44 110.2 180 top
R28  10k  [0402]  32.44 109.06 180 top
R29  10k  [0402]  29.77 113.25 0 top
R30  8.06k  [0402]  110.24 39.24 270 top
R31  1M  [0402]  100.08 37.08 270 top
R32  1.2k  [0402]  101.73 45.21 90 top
R33  1.33k  [0402]  112.52 39.24 90 top
R34  0  [0402]  11.81 43.05 0 top
R35  0  [0402]  12.32 42.55 90 top
R36  0  [0402]  12.32 40.51 270 top
R37  750  [0402]  32.44 107.91 180 top
R38  0  [0402]  11.81 40 0 top
R39  1.3k  [0402]  32.44 111.34 180 top
R40  0  [0402]  28.94 98.45 180 bottom
R41  1.3k  [0402]  32.44 112.49 180 top
R42  0  [0402]  28.94 103.79 180 bottom
R43  100  [0402]  20.7 73.28 90 top
R44  49.9  [0402]  56.87 116.4 90 bottom
R45  49.9  [0402]  56.87 114.37 270 bottom
R46  12k  [0402]  67.67 119.32 0 bottom
R47  100  [0402]  57.23 111.81 180 bottom
R48  49.9  [0402]  61.52 111.63 180 bottom
R49  49.9  [0402]  59.49 111.63 0 bottom
R50  680  [0201]  58.85 121.94 0 bottom
R51  680  [0201]  54.33 120.21 0 top
R52  49.9  [0201]  62.03 108.91 90 bottom
R53  49.9  [0201]  58.98 108.91 90 bottom
R54  0  [0201]  67.39 121.96 180 bottom
R55  12  [0201]  65.86 121.96 180 bottom
R56  150  [0201]  69.67 122.75 180 bottom
R57  240  [0201]  94.2 111.46 90 bottom
R58  240  [0201]  94.2 110.19 270 bottom
R59  0  [0201]  107.42 104.67 0 bottom
R60  0  [0201]  107.42 103.91 0 bottom
R61  240  [0201]  106.4 103.65 270 bottom
R62  240  [0201]  106.4 104.92 90 bottom
R63  39k  [0201]  93.96 93.92 180 bottom
R64  240  [0201]  106.4 106.14 270 bottom
R65  240  [0201]  106.4 107.41 90 bottom
R66  620  [0201]  88.62 106.88 90 bottom
R67  0  [0402]  79.48 97.73 270 bottom
R68  49.9  [0201]  88.5 98.88 270 bottom
R69  0  [0603]  83.67 98.24 0 bottom
R70  18  [0402]  76.68 98.24 0 bottom
R71  292  [0402]  75.03 97.73 270 bottom
R72  292  [0402]  78.34 97.73 270 bottom
R73  100  [0402]  87.35 99.51 90 bottom
R74  120  [0201]  105.29 95.27 0 bottom
R75  120  [0201]  104.02 95.27 180 bottom
R76  0  [0201]  107.58 96.42 270 bottom
R77  0  [0201]  106.81 96.42 270 bottom
R78  120  [0201]  107.83 97.43 0 bottom
R79  120  [0201]  106.56 97.43 180 bottom
R80  100  [0201]  106.56 95.4 180 bottom
R81  100  [0201]  107.83 95.4 0 bottom
R82  130  [0201]  86.97 103.43 90 bottom
R83  100  [0201]  84.56 103.7 0 bottom
R84  82  [0201]  83.54 103.45 270 bottom
R85  49.9  [0201]  87.73 103.43 270 bottom
R86  240  [0201]  96.37 108.78 180 bottom
R87  240  [0201]  97.64 108.78 0 bottom
R88  130  [0201]  86.97 104.7 270 bottom
R89  240  [0201]  100.39 111.25 180 bottom
R90  240  [0201]  101.66 111.25 0 bottom
R91  100  [0201]  84.56 104.46 0 bottom
R92  82  [0201]  83.54 104.72 90 bottom
R93  49.9  [0201]  87.73 104.7 90 bottom
R94  240  [0201]  97.18 95.7 0 bottom
R95  240  [0201]  95.81 95.7 180 bottom
R96  2.32k  [0402]  107.67 102.43 270 top
R97  0  [0402]  128.4 71.25 0 top
R98  0  [0402]  125.86 50.8 0 top
R99  10k  [0402]  105.26 103.96 0 top
R100  750  [0603]  50.87 119.2 0 bottom
R101  750  [0603]  50.87 116.4 0 bottom
R102  750  [0603]  50.87 121.99 0 bottom
R103  750  [0603]  50.87 113.61 0 bottom
R104  4.99k  [0402]  136.83 89.31 180 top
R105  0  [0402]  139.06 36.83 270 top
R106  100  [0603]  132.59 90.02 180 top
R107  0  [0402]  132.72 37.46 180 top
R108  100  [0201]  119.25 93.9 90 top
R109  270  [0402]  52.96 50.52 0 bottom
R110  100  [0402]  66.55 29.4 180 bottom
R111  0  [0603]  17.91 15.75 180 top
R112  100  [0402]  59.82 31.11 270 top
R113  100  [0402]  60.96 31.11 270 top
R114  10k  [0402]  68.45 41.27 180 top
R115  10k  [0402]  68.45 38.99 180 top
R116  10  [0603]  10.92 25.65 90 top
R117  10  [0603]  12.45 25.65 90 top
R118  100  [0402]  68.45 36.7 0 top
R119  100  [0402]  68.45 37.85 0 top
R120  100  [0402]  70.48 38.99 0 top
R121  100  [0402]  70.48 40.13 0 top
R122  12k  [0603]  55.24 40.39 180 bottom
R123  10k  [0402]  79.32 43.12 0 top
R124  10k  [0402]  74.87 45.36 0 top
R125  10k  [0402]  74.87 46.5 0 top
R126  0  [0201]  100.64 112.26 90 bottom
R127  0  [0201]  101.4 112.26 90 bottom
R128  0  [0201]  107.42 107.16 0 bottom
R129  0  [0201]  107.42 106.4 0 bottom
R130  1k  [0603]  51.82 36.36 0 top
R131  2.2k  [0603]  79.01 44.7 0 top
R132  10k  [0402]  53.34 26.29 0 bottom
R133  100  [0402]  57.91 29.59 0 top
R134  100  [0402]  57.91 28.45 0 top
R135  100  [0402]  57.91 27.3 0 top
R136  100  [0402]  57.91 26.16 0 top
R137  100  [0402]  57.91 25.02 0 top
R138  1k  [0402]  86.86 40.04 0 top
R139  1k  [0402]  86.86 38.9 0 top
R140  1k  [0402]  86.86 37.76 0 top
R141  1k  [0402]  86.86 36.61 0 top
R142  100  [0402]  86.86 35.47 0 top
R143  1k  [0402]  91.2 49.78 0 top
R144  1k  [0402]  91.2 48.64 0 top
R145  1k  [0402]  91.2 47.49 0 top
R146  1k  [0402]  91.2 46.35 0 top
R147  100  [0402]  91.2 45.21 0 top
R148  1K  [0402]  29.46 6.6 90 bottom
R149  36.5k  [0402]  47.62 20.83 0 bottom
R150  1M  [0402]  40.77 2.79 270 top
R151  0  [0201]  27.58 62.41 270 top
R152  287k  [0402]  38.99 3.28 180 top
R153  162k  [0402]  38.99 2.13 0 top
R154  0  [0402]  52.47 18.43 180 bottom
R155  0  [0402]  52.47 17.26 180 bottom
R156  0  [0402]  52.47 16.12 180 bottom
R157  0  [0402]  52.47 14.98 180 bottom
R158  0  [0805]  63.75 14.22 180 bottom
R159  0  [0805]  68 14.25 180 bottom
R160  124k  [0402]  53.22 3.09 180 top
R161  2k  [0603]  70.61 7.75 90 bottom
R162  0  [0201]  27.58 58.75 90 top
R163  0  [0805]  73.53 8 270 bottom
R164  1M  [0402]  51.56 2.54 90 top
R165  2.4k  [0402]  70.48 4.83 270 bottom
R166  162k  [0402]  53.21 1.9 0 top
R167  47k  [0603]  61.72 8.25 270 bottom
R168  4.99k  [0603]  70.61 10.79 90 bottom
R169  4.75k  [0402]  70.48 2.67 270 bottom
R170  0  [0402]  101.27 3.96 270 top
R171  0  [0402]  102.39 3.96 270 top
R172  0  [0402]  103.5 3.96 90 top
R173  0  [0402]  102.62 5.82 0 top
R174  0  [0402]  84.38 3.96 270 top
R175  0  [0402]  85.5 3.96 270 top
R176  0  [0402]  86.61 3.96 90 top
R177  0  [0402]  85.72 5.82 0 top
R178  100  [0402]  66.17 41.27 0 top
R179  0  [0201]  27.58 87.81 270 top
R180  0  [0201]  27.58 84.15 90 top
R183  0  [0402]  52.45 19.56 180 bottom
R184  1M  [0402]  110.87 35.81 270 top
R185  1.2k  [0402]  109.98 45.34 90 top
R186  0  [0201]  88.37 101.29 0 bottom
R187  51  [0201]  87.35 101.24 270 bottom
R188  240  [0201]  91.16 102.94 180 bottom
R189  240  [0201]  91.16 102.18 180 bottom
SJP1  SOLDER JUMPER, 0402  [SMD_JUMPER_L_0402]  79.73 123.39 270 top
SJP2  SOLDER JUMPER, 0402  [SMD_JUMPER_L_0402]  43.31 11.68 270 top
SJP3  SOLDER JUMPER, 0402  [SMD_JUMPER_L_0402]  61.72 8.13 90 top
SJP4  SOLDER JUMPER, 0402  [SMD_JUMPER_L_0402]  64.01 11.05 0 top
T1  TC1-1-13M+  [TFMR_5_150X150_50]  83.54 99.51 0 bottom
T2  TC1-1-43X+  [TFMR_5_150X150_50]  17.27 73.28 0 top
TP1  ORN  [TP_THVT_100_RND]  33.96 117.06 0 top
TP2  ORN  [TP_THVT_100_RND]  30.15 117.06 0 top
TP3  ORN  [TP_THVT_100_RND]  26.34 117.06 0 top
TP4  ORN  [TP_THVT_100_RND]  113.41 51.44 0 top
TP5  PROBE POINT  [PROBE_POINT_30PAD]  121.28 32.64 0 top
TP6  PROBE POINT  [PROBE_POINT_30PAD]  116.46 32.64 0 top
TP7  PROBE POINT  [PROBE_POINT_30PAD]  44.07 37.21 0 top
TP10  PROBE POINT  [PROBE_POINT_30PAD]  44.07 33.4 0 top
TP11  PROBE POINT  [PROBE_POINT_30PAD]  44.07 25.78 0 top
TP12  RED  [TP_THVT_125_RND_063D]  23.37 18.8 0 top
TP13  BLK  [TP_THVT_125_RND_063D]  18.03 18.8 0 top
TP14  PROBE POINT  [PROBE_POINT_30PAD]  39.12 22.73 0 top
TP15  RED  [TP_THVT_100_RND]  47.24 5.46 0 top
TP16  BLK  [TP_THVT_100_RND]  99.85 49.75 0 top
TP17  PROBE POINT  [PROBE_POINT_30PAD]  60.71 3.3 0 top
TP18  BLK  [TP_THVT_100_RND]  90.04 14.6 0 top
TP19  PROBE POINT  [PROBE_POINT_30PAD]  68.07 19.05 0 top
TP20  PROBE POINT  [PROBE_POINT_30PAD]  75.44 18.54 0 top
TP21  BLK  [TP_THVT_100_RND]  22.53 117.06 0 top
TP22  PROBE POINT  [PROBE_POINT_30PAD]  103.76 17.78 0 top
TP23  PROBE POINT  [PROBE_POINT_30PAD]  98.42 19.43 0 top
TP24  PROBE POINT  [PROBE_POINT_30PAD]  89.66 18.16 0 top
TP25  ORN  [TP_THVT_100_RND]  23.5 103.63 0 top
TP26  ORN  [TP_THVT_100_RND]  18.29 103.63 0 top
TP27  PROBE POINT  [PROBE_POINT_30PAD]  82.68 17.91 0 top
TP28  BLK  [TP_THVT_100_RND]  13.72 103.63 0 top
TP29  BLK  [TP_THVT_100_RND]  59.44 18.92 0 top
TP30  BLK  [TP_THVT_100_RND]  110.45 18.59 0 top
TP31  PROBE POINT  [PROBE_POINT_30PAD]  30.33 81.92 0 top
TP32  PROBE POINT  [PROBE_POINT_30PAD]  40.77 114.17 0 top
TP33  PROBE POINT  [PROBE_POINT_30PAD]  45.21 103.25 0 top
TP36  GRN  [TP_THVT_100_RND]  72.39 30.35 0 top
U1  ADC12DJXX00  [BGA_144_10MMX10MM_0P80MM]  34.92 73.28 270 top
U2  LM95233  [WSON_14_4MMX4MM_0P5]  28.37 110.2 0 top
U3  LMX2582  [QFN40_RTA_RTB_RHA]  62.05 116.89 180 bottom
U4  LMK04828  [QFN_64_360X360_0P50MM_PWRPAD]  98.02 102.56 180 bottom
U5  24LC65  [SO_8_207X207_50]  119.13 40.26 270 top
U6  TLV70233  [SOT_5_120X69_37]  32 15.75 0 top
U7  SN74LVC1G125DBVR  [SOT_5_120X69_57]  65.53 30.35 270 top
U8  FT4232HQ  [QFN_64_0P50MM_RGC_FT2232HQ]  59.05 39.12 0 top
U9  93LC46B-I  [MSOP_8_118X118_0P65MM]  77.99 48.51 90 top
U10  SN74AVC4T774  [TSSOP_16_201X177_26]  51.49 27.3 0 top
U11  SN74AVC4T774  [TSSOP_16_201X177_26]  80.43 37.76 0 top
U12  SN74AVC4T774  [TSSOP_16_201X177_26]  84.77 47.49 0 top
U13  TPS2400  [DBV5]  23.37 12.95 90 top
U14  TPS62085  [QFN_7_2MMX2MM]  38.27 5.76 90 top
U15  LMC6762  [SOIC_8_197X157_50]  105.54 38.23 0 top
U16  TPS7A7200  [QFN_20_199X199_0P65MM]  47.87 16.71 270 bottom
U17  TPS62085  [QFN_7_2MMX2MM]  52.58 5.21 90 top
U20  TPS74401MRGWREP  [QFN_20_197X197_0P65_RGW]  66.09 8.41 90 bottom
U21  TPS7A4700  [QFN_20_199X199_0P65MM]  100.79 5.79 270 bottom
U22  TPS7A4700  [QFN_20_199X199_0P65MM]  83.9 5.79 270 bottom
Y1  100.00MHz  [VCXO_6_CUSTOM]  79.61 115.01 270 bottom
Y2  12MHz, 18pF  [XTAL_2_SM_126X197]  48.26 42.55 90 top

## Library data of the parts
BALUN1 BALUN2 = BALUN_MARKI_SMG_320x320
C1 C42 C172 C177 C190-C195 = CAP_0603_0.1uF
C2 C173 C175 C180 = CAP_0603_1uF
C3 C4 C14 C45 C47-C53 = CAP_0402_4700pF_H
C5-C13 C15 C16 C18 C19 C21-C23 C25-C40 C138 C144 C149 = CAP_0402_0.1uF_H: tolerance: 10%
C20 C24 C100 C101 C103 C104 C106 C107 C109 C113 C133 C135 C142 C143 C146 C151 C153-C163 C165 C166 C249 C250 = CAPACITOR_NP_1: tolerance: 10%
C41 C44 C46 = CAP_0603_100pF
C43 C68 C83 C95 = CAP_TANT_B_10uF_10V: tolerance: 20%
C54-C65 C69-C80 C84-C92 C96 = CAP0402_0: tolerance: 10%
C66 C67 C81 C82 C93 C94 C112 C115 C116 C118 C198 C201 C205 C208 C209 C215 C217 C220 C224 C225 C238 = CAP NP_1: tolerance: 10%
C99 C105 C108 C110 C139 = CAP_0603_100pF_H
C102 C111 C114 C117 C119-C122 C128 C130 C131 C145 C150 C210 C213 C214 C227 C235 C240 C246 = CAP NP_0: tolerance: 10%
C132 = CAP NP_0: tolerance: 5%
C134 C136 = CAP_0402_0.01uF_H: tolerance: 10%
C137 = CAP_0402_0.1uF: tolerance: 10%
C140 = CAP_0402_2200pF_H
C141 = CAP_0402_10pF_H
C152 = CAPACITOR_NP_1: tolerance: 2%
C164 = CAP NP_2: tolerance: 10%
C167 = CAP NP_1
C168 C170 C179 = CAP_0603_10uF
C169 C171 C176 C181-C183 C186-C189 = CAP_0201_0.1uF
C174 C178 = CAP_1206_100uF_6.3V
C184 C185 = CAP_0402_18pF
C196 = CAP POL-B_0: tolerance: 10%
C200 C202 C204 C218 C219 C222 C223 C229 C242 = CAP0201_0: tolerance: 20%
C203 C226 C233 C237 C239 C244 = CAP0603: tolerance: 10%
C206 C211 = CAP: tolerance: 10%
C207 C228 C241 = CAP NP_0: tolerance: 20%
C212 = CAP_0603_2.2uF
C216 = CAP_0603_.47uF
C221 = CAP_0603_1000pF
C230 C236 C243 C247 = CAP0201_0: tolerance: 10%
C234 C245 C248 = CAP0402_0: tolerance: 10V
D1 = LED_RED_0
D2-D6 = LED
D7 D8 = LED_GREEN_0
D9 D12 = DIODE_1N4148W
D10 D11 = LED_ORANGE_0603
D13 = DIODE_MBRB2515L
F1 = FUSE_0
FB1-FB11 FB20-FB23 = FERRITE_BEAD_0402_H
FB12 FB13 = FERRITE_BEAD_0603_120_H
FB14 = FERRITE_BEAD_0603_26_H
FB16-FB19 = BEAD_NFM31P
J1 J3 J4 J6 J23 J24 = SMA_THVT_SMA_CENTER_PIN
J2 J5 J14 J15 J18 = SMA_END_HIGH_FREQ_PSF-S01_0
J7 = HEADER_2x4_100
J8 J9 J17 = HEADER_1x2_100
J20 = SMP_PLUG_SMT_0
J22 J38 = SMA-THVT_142-0701-201_REC_0
J25 = CON_SMVT_40X14_50_M
J26 J27 J30 JP7-JP9 = JUMPER_1X2_100
J28 = HEADER_1x4_100
J31 = USB_MINI_AB_MNE20-5G5P10
J37 = CONN JACK PWR
JP5 = HDR_2x1_100
JP6 = JUMPER_1X3_100
L3 L4 = CHOKE
MT1 MT2 = MOUNTING_HOLE
Q1 = NPN_MMBT3904
Q3 = CSD18532Q5B
R1 R4 R6 R9 R151 R162 R179 R180 = Res_0201_Zero_H
R11 R12 R17 R18 R21 R23 R27-R29 R114 R115 R123-R125 R132 = Res_0402_10k
R13-R16 = Res_0402_1k_H
R19 R20 R25 = Res_0402_1k
R22 R24 R54 R59 R60 R76 R77 R126-R129 R158 R159 R163 R186 = Res_0402_Zero_H_DNI
R26 = Res_0402_2.1K
R30 = Res_0402_8.06k
R31 R184 = Res_0402_1M
R32 R185 = Res_0402_1.2k
R33 = Res_0402_1.33k
R34-R36 R38 R40 R42 R97 R98 R149 = Res_0402_Zero_H
R37 = Res_0603_750_H
R39 R41 = Res_0603_1.3k_H
R43 R47 R83 R91 = Res_0402_100_H
R44 R45 R48-R53 R68 = Res_0402_49.9
R46 R55 R70 = Res_0402_18
R56 R63 R66 = R_1
R57 R58 R61 R62 R64 R65 R74 R75 R78 R79 R86 R87 R89 R90 R94 R95 R188 R189 = Res_0402_249
R67 R166 R170-R177 = R
R69 = Res_0603_Zero_DNI
R71 R72 R109 = Res_0402_270
R73 R80 R81 = Res_0603_100
R82 R100-R103 = RESISTOR_0
R84 R85 R88 R92 R93 = RESISTOR_0: tolerance: 1%
R96 = Res_0402_2.32K_H
R99 = Res_0402_1.3K
R104 = Res_0402_4.99K
R105 R107 = Res_0402_Zero
R106 R108 = Res_0201_100
R110 R112 R113 R118-R121 R133-R137 R142 R147 R178 = Res_0603_100_H
R111 = Res_0603_Zero
R116 R117 = Res_0603_10
R122 = Res_0603_12k
R130 R138-R141 R143-R146 = Res_0603_1k_H
R131 = Res_0603_2.2k
R148 = Res_0402_1k: tolerance: 1%
R150 R153 R164 = R: tolerance: 1%
R152 R160 = Res_0603_Zero_H
R154-R157 R183 = R: tolerance: 5%
R161 = Res_0603_1.87K
R165 = Res_0603_12.4k
R167 = Res_0603_47K
R168 = Res_0603_4.99K
R169 = Res_0603_10k
R187 = Res_0201_51_1%
SJP1-SJP4 = SMD_JUMPER_1x3
T1 = TFMR_5_TC1-1-13M+
T2 = TFMR_5_TC1-1-43X+
TP1-TP3 TP25 TP26 = TESTPOINT_ORANGE
TP4 = TESTPOINT_BLUE
TP5-TP7 TP10 TP11 TP14 TP17 TP19 TP20 TP22-TP24 TP27 TP31-TP33 = PROBE_POINT_0
TP12 TP13 = TESTLOOP_BLACK
TP15 = TESTLOOP_RED
TP16 TP18 TP21 TP28-TP30 = TESTPOINT_BLK
TP36 = TESTPOINT_GRN
U1 = ADC12DJXX00
U2 = LM95233
U3 = LMX2582_LM2592
U4 = LMK04828
U5 = 24LC65
U6 = TLV702
U7 = SN74LVC1G125DBVR
U8 = FT4232HQ
U9 = EEPROM_93LC46B
U10-U12 = SN74AVC4T774
U13 = TPS2400
U14 U17 = TPS62085/62086/62087
U15 = LMC6762
U16 = TPS7A7300
U20 = TPS74401
U21 U22 = TPS7A4700
Y1 = OSC_SM_6_TCO-2100-SERIES_2
Y2 = CRYSTAL_ABM3_0

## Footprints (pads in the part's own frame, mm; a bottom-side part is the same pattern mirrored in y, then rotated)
0201
  rect 0.305x0.305 smd: 1(-0.305,0) 2(0.305,0)
0402
  rect 0.508x0.635 smd: 1(-0.508,0) 2(0.508,0)
0603
  rect 0.762x0.813 smd: 1(-0.787,0) 2(0.787,0)
0805
  rect 1.016x1.27 smd: 1(-1.016,0) 2(1.016,0)
1206
  rect 1.27x1.6 smd: 1(-1.524,0) 2(1.524,0)
1206_BEAD_NFM31P
  rect 1.016x1.575 smd: 1(-1.778,0) 3(1.778,0)
  rect 1.321x2.032 smd: 2(0,0)
BALUN_320X320_MARKI_0006SMG
  round 0.533 smd: 1(0,4.216) 2(1.524,-4.216) 3(-1.524,-4.216)
BGA_144_10MMX10MM_0P80MM
  round 0.457 smd: A1(-4.4,-4.4) A2(-4.4,-3.6) A3(-4.4,-2.8) A4(-4.4,-2) A5(-4.4,-1.2) A6(-4.4,-0.4) A7(-4.4,0.4) A8(-4.4,1.2) A9(-4.4,2) A10(-4.4,2.8) A11(-4.4,3.6) A12(-4.4,4.4) B1(-3.6,-4.4) B2(-3.6,-3.6) B3(-3.6,-2.8) B4(-3.6,-2) B5(-3.6,-1.2) B6(-3.6,-0.4) B7(-3.6,0.4) B8(-3.6,1.2) B9(-3.6,2) B10(-3.6,2.8) B11(-3.6,3.6) B12(-3.6,4.4) C1(-2.8,-4.4) C2(-2.8,-3.6) C3(-2.8,-2.8) C4(-2.8,-2) C5(-2.8,-1.2) C6(-2.8,-0.4) C7(-2.8,0.4) C8(-2.8,1.2) C9(-2.8,2) C10(-2.8,2.8) C11(-2.8,3.6) C12(-2.8,4.4) D1(-2,-4.4) D2(-2,-3.6) D3(-2,-2.8) D4(-2,-2) D5(-2,-1.2) D6(-2,-0.4) D7(-2,0.4) D8(-2,1.2) D9(-2,2) D10(-2,2.8) D11(-2,3.6) D12(-2,4.4) E1(-1.2,-4.4) E2(-1.2,-3.6) E3(-1.2,-2.8) E4(-1.2,-2) E5(-1.2,-1.2) E6(-1.2,-0.4) E7(-1.2,0.4) E8(-1.2,1.2) E9(-1.2,2) E10(-1.2,2.8) E11(-1.2,3.6) E12(-1.2,4.4) F1(-0.4,-4.4) F2(-0.4,-3.6) F3(-0.4,-2.8) F4(-0.4,-2) F5(-0.4,-1.2) F6(-0.4,-0.4) F7(-0.4,0.4) F8(-0.4,1.2) F9(-0.4,2) F10(-0.4,2.8) F11(-0.4,3.6) F12(-0.4,4.4) G1(0.4,-4.4) G2(0.4,-3.6) G3(0.4,-2.8) G4(0.4,-2) G5(0.4,-1.2) G6(0.4,-0.4) G7(0.4,0.4) G8(0.4,1.2) G9(0.4,2) G10(0.4,2.8) G11(0.4,3.6) G12(0.4,4.4) H1(1.2,-4.4) H2(1.2,-3.6) H3(1.2,-2.8) H4(1.2,-2) H5(1.2,-1.2) H6(1.2,-0.4) H7(1.2,0.4) H8(1.2,1.2) H9(1.2,2) H10(1.2,2.8) H11(1.2,3.6) H12(1.2,4.4) J1(2,-4.4) J2(2,-3.6) J3(2,-2.8) J4(2,-2) J5(2,-1.2) J6(2,-0.4) J7(2,0.4) J8(2,1.2) J9(2,2) J10(2,2.8) J11(2,3.6) J12(2,4.4) K1(2.8,-4.4) K2(2.8,-3.6) K3(2.8,-2.8) K4(2.8,-2) K5(2.8,-1.2) K6(2.8,-0.4) K7(2.8,0.4) K8(2.8,1.2) K9(2.8,2) K10(2.8,2.8) K11(2.8,3.6) K12(2.8,4.4) L1(3.6,-4.4) L2(3.6,-3.6) L3(3.6,-2.8) L4(3.6,-2) L5(3.6,-1.2) L6(3.6,-0.4) L7(3.6,0.4) L8(3.6,1.2) L9(3.6,2) L10(3.6,2.8) L11(3.6,3.6) L12(3.6,4.4) M1(4.4,-4.4) M2(4.4,-3.6) M3(4.4,-2.8) M4(4.4,-2) M5(4.4,-1.2) M6(4.4,-0.4) M7(4.4,0.4) M8(4.4,1.2) M9(4.4,2) M10(4.4,2.8) M11(4.4,3.6) M12(4.4,4.4)
CON_RAPC722_JACK_THVT_3
  round 4.318 hole 3.556: 1(0,3.124)
  round 3.81 hole 3.048: 2(0,-3.124) 3(4.801,0.127)
CON_SMRT_USBMNE20_F
  round 0.025 hole 0.991 unplated: (0.65,2.2) (0.65,-2.2)
  rect 2.311x0.508 smd: 1(3.45,1.6) 2(3.45,0.8) 3(3.45,0) 4(3.45,-0.8) 5(3.45,-1.6)
  rect 2.489x2.007 smd: 6(-2.15,-4.45) 7(3.35,-4.45) 8(3.35,4.45) 9(-2.15,4.45)
CON_SMVT_40X14_50_M_MTG
  round 3.81 hole 2.692: (-31.496,-2.007) (31.496,-2.007)
  round 1.27 hole 1.27 unplated: (-27.191,-3.048) (27.191,0)
  round 0.635 smd: A1(24.765,5.715) A2(23.495,5.715) A3(22.225,5.715) A4(20.955,5.715) A5(19.685,5.715) A6(18.415,5.715) A7(17.145,5.715) A8(15.875,5.715) A9(14.605,5.715) A10(13.335,5.715) A11(12.065,5.715) A12(10.795,5.715) A13(9.525,5.715) A14(8.255,5.715) A15(6.985,5.715) A16(5.715,5.715) A17(4.445,5.715) A18(3.175,5.715) A19(1.905,5.715) A20(0.635,5.715) A21(-0.635,5.715) A22(-1.905,5.715) A23(-3.175,5.715) A24(-4.445,5.715) A25(-5.715,5.715) A26(-6.985,5.715) A27(-8.255,5.715) A28(-9.525,5.715) A29(-10.795,5.715) A30(-12.065,5.715) A31(-13.335,5.715) A32(-14.605,5.715) A33(-15.875,5.715) A34(-17.145,5.715) A35(-18.415,5.715) A36(-19.685,5.715) A37(-20.955,5.715) A38(-22.225,5.715) A39(-23.495,5.715) A40(-24.765,5.715) B1(24.765,4.445) B2(23.495,4.445) B3(22.225,4.445) B4(20.955,4.445) B5(19.685,4.445) B6(18.415,4.445) B7(17.145,4.445) B8(15.875,4.445) B9(14.605,4.445) B10(13.335,4.445) B11(12.065,4.445) B12(10.795,4.445) B13(9.525,4.445) B14(8.255,4.445) B15(6.985,4.445) B16(5.715,4.445) B17(4.445,4.445) B18(3.175,4.445) B19(1.905,4.445) B20(0.635,4.445) B21(-0.635,4.445) B22(-1.905,4.445) B23(-3.175,4.445) B24(-4.445,4.445) B25(-5.715,4.445) B26(-6.985,4.445) B27(-8.255,4.445) B28(-9.525,4.445) B29(-10.795,4.445) B30(-12.065,4.445) B31(-13.335,4.445) B32(-14.605,4.445) B33(-15.875,4.445) B34(-17.145,4.445) B35(-18.415,4.445) B36(-19.685,4.445) B37(-20.955,4.445) B38(-22.225,4.445) B39(-23.495,4.445) B40(-24.765,4.445) C1(24.765,3.175) C2(23.495,3.175) C3(22.225,3.175) C4(20.955,3.175) C5(19.685,3.175) C6(18.415,3.175) C7(17.145,3.175) C8(15.875,3.175) C9(14.605,3.175) C10(13.335,3.175) C11(12.065,3.175) C12(10.795,3.175) C13(9.525,3.175) C14(8.255,3.175) C15(6.985,3.175) C16(5.715,3.175) C17(4.445,3.175) C18(3.175,3.175) C19(1.905,3.175) C20(0.635,3.175) C21(-0.635,3.175) C22(-1.905,3.175) C23(-3.175,3.175) C24(-4.445,3.175) C25(-5.715,3.175) C26(-6.985,3.175) C27(-8.255,3.175) C28(-9.525,3.175) C29(-10.795,3.175) C30(-12.065,3.175) C31(-13.335,3.175) C32(-14.605,3.175) C33(-15.875,3.175) C34(-17.145,3.175) C35(-18.415,3.175) C36(-19.685,3.175) C37(-20.955,3.175) C38(-22.225,3.175) C39(-23.495,3.175) C40(-24.765,3.175) D1(24.765,1.905) D2(23.495,1.905) D3(22.225,1.905) D4(20.955,1.905) D5(19.685,1.905) D6(18.415,1.905) D7(17.145,1.905) D8(15.875,1.905) D9(14.605,1.905) D10(13.335,1.905) D11(12.065,1.905) D12(10.795,1.905) D13(9.525,1.905) D14(8.255,1.905) D15(6.985,1.905) D16(5.715,1.905) D17(4.445,1.905) D18(3.175,1.905) D19(1.905,1.905) D20(0.635,1.905) D21(-0.635,1.905) D22(-1.905,1.905) D23(-3.175,1.905) D24(-4.445,1.905) D25(-5.715,1.905) D26(-6.985,1.905) D27(-8.255,1.905) D28(-9.525,1.905) D29(-10.795,1.905) D30(-12.065,1.905) D31(-13.335,1.905) D32(-14.605,1.905) D33(-15.875,1.905) D34(-17.145,1.905) D35(-18.415,1.905) D36(-19.685,1.905) D37(-20.955,1.905) D38(-22.225,1.905) D39(-23.495,1.905) D40(-24.765,1.905) E1(24.765,0.635) E2(23.495,0.635) E3(22.225,0.635) E4(20.955,0.635) E5(19.685,0.635) E6(18.415,0.635) E7(17.145,0.635) E8(15.875,0.635) E9(14.605,0.635) E10(13.335,0.635) E11(12.065,0.635) E12(10.795,0.635) E13(9.525,0.635) E14(8.255,0.635) E15(6.985,0.635) E16(5.715,0.635) E17(4.445,0.635) E18(3.175,0.635) E19(1.905,0.635) E20(0.635,0.635) E21(-0.635,0.635) E22(-1.905,0.635) E23(-3.175,0.635) E24(-4.445,0.635) E25(-5.715,0.635) E26(-6.985,0.635) E27(-8.255,0.635) E28(-9.525,0.635) E29(-10.795,0.635) E30(-12.065,0.635) E31(-13.335,0.635) E32(-14.605,0.635) E33(-15.875,0.635) E34(-17.145,0.635) E35(-18.415,0.635) E36(-19.685,0.635) E37(-20.955,0.635) E38(-22.225,0.635) E39(-23.495,0.635) E40(-24.765,0.635) F1(24.765,-0.635) F2(23.495,-0.635) F3(22.225,-0.635) F4(20.955,-0.635) F5(19.685,-0.635) F6(18.415,-0.635) F7(17.145,-0.635) F8(15.875,-0.635) F9(14.605,-0.635) F10(13.335,-0.635) F11(12.065,-0.635) F12(10.795,-0.635) F13(9.525,-0.635) F14(8.255,-0.635) F15(6.985,-0.635) F16(5.715,-0.635) F17(4.445,-0.635) F18(3.175,-0.635) F19(1.905,-0.635) F20(0.635,-0.635) F21(-0.635,-0.635) F22(-1.905,-0.635) F23(-3.175,-0.635) F24(-4.445,-0.635) F25(-5.715,-0.635) F26(-6.985,-0.635) F27(-8.255,-0.635) F28(-9.525,-0.635) F29(-10.795,-0.635) F30(-12.065,-0.635) F31(-13.335,-0.635) F32(-14.605,-0.635) F33(-15.875,-0.635) F34(-17.145,-0.635) F35(-18.415,-0.635) F36(-19.685,-0.635) F37(-20.955,-0.635) F38(-22.225,-0.635) F39(-23.495,-0.635) F40(-24.765,-0.635) G1(24.765,-1.905) G2(23.495,-1.905) G3(22.225,-1.905) G4(20.955,-1.905) G5(19.685,-1.905) G6(18.415,-1.905) G7(17.145,-1.905) G8(15.875,-1.905) G9(14.605,-1.905) G10(13.335,-1.905) G11(12.065,-1.905) G12(10.795,-1.905) G13(9.525,-1.905) G14(8.255,-1.905) G15(6.985,-1.905) G16(5.715,-1.905) G17(4.445,-1.905) G18(3.175,-1.905) G19(1.905,-1.905) G20(0.635,-1.905) G21(-0.635,-1.905) G22(-1.905,-1.905) G23(-3.175,-1.905) G24(-4.445,-1.905) G25(-5.715,-1.905) G26(-6.985,-1.905) G27(-8.255,-1.905) G28(-9.525,-1.905) G29(-10.795,-1.905) G30(-12.065,-1.905) G31(-13.335,-1.905) G32(-14.605,-1.905) G33(-15.875,-1.905) G34(-17.145,-1.905) G35(-18.415,-1.905) G36(-19.685,-1.905) G37(-20.955,-1.905) G38(-22.225,-1.905) G39(-23.495,-1.905) G40(-24.765,-1.905) H1(24.765,-3.175) H2(23.495,-3.175) H3(22.225,-3.175) H4(20.955,-3.175) H5(19.685,-3.175) H6(18.415,-3.175) H7(17.145,-3.175) H8(15.875,-3.175) H9(14.605,-3.175) H10(13.335,-3.175) H11(12.065,-3.175) H12(10.795,-3.175) H13(9.525,-3.175) H14(8.255,-3.175) H15(6.985,-3.175) H16(5.715,-3.175) H17(4.445,-3.175) H18(3.175,-3.175) H19(1.905,-3.175) H20(0.635,-3.175) H21(-0.635,-3.175) H22(-1.905,-3.175) H23(-3.175,-3.175) H24(-4.445,-3.175) H25(-5.715,-3.175) H26(-6.985,-3.175) H27(-8.255,-3.175) H28(-9.525,-3.175) H29(-10.795,-3.175) H30(-12.065,-3.175) H31(-13.335,-3.175) H32(-14.605,-3.175) H33(-15.875,-3.175) H34(-17.145,-3.175) H35(-18.415,-3.175) H36(-19.685,-3.175) H37(-20.955,-3.175) H38(-22.225,-3.175) H39(-23.495,-3.175) H40(-24.765,-3.175) J1(24.765,-4.445) J2(23.495,-4.445) J3(22.225,-4.445) J4(20.955,-4.445) J5(19.685,-4.445) J6(18.415,-4.445) J7(17.145,-4.445) J8(15.875,-4.445) J9(14.605,-4.445) J10(13.335,-4.445) J11(12.065,-4.445) J12(10.795,-4.445) J13(9.525,-4.445) J14(8.255,-4.445) J15(6.985,-4.445) J16(5.715,-4.445) J17(4.445,-4.445) J18(3.175,-4.445) J19(1.905,-4.445) J20(0.635,-4.445) J21(-0.635,-4.445) J22(-1.905,-4.445) J23(-3.175,-4.445) J24(-4.445,-4.445) J25(-5.715,-4.445) J26(-6.985,-4.445) J27(-8.255,-4.445) J28(-9.525,-4.445) J29(-10.795,-4.445) J30(-12.065,-4.445) J31(-13.335,-4.445) J32(-14.605,-4.445) J33(-15.875,-4.445) J34(-17.145,-4.445) J35(-18.415,-4.445) J36(-19.685,-4.445) J37(-20.955,-4.445) J38(-22.225,-4.445) J39(-23.495,-4.445) J40(-24.765,-4.445) K1(24.765,-5.715) K2(23.495,-5.715) K3(22.225,-5.715) K4(20.955,-5.715) K5(19.685,-5.715) K6(18.415,-5.715) K7(17.145,-5.715) K8(15.875,-5.715) K9(14.605,-5.715) K10(13.335,-5.715) K11(12.065,-5.715) K12(10.795,-5.715) K13(9.525,-5.715) K14(8.255,-5.715) K15(6.985,-5.715) K16(5.715,-5.715) K17(4.445,-5.715) K18(3.175,-5.715) K19(1.905,-5.715) K20(0.635,-5.715) K21(-0.635,-5.715) K22(-1.905,-5.715) K23(-3.175,-5.715) K24(-4.445,-5.715) K25(-5.715,-5.715) K26(-6.985,-5.715) K27(-8.255,-5.715) K28(-9.525,-5.715) K29(-10.795,-5.715) K30(-12.065,-5.715) K31(-13.335,-5.715) K32(-14.605,-5.715) K33(-15.875,-5.715) K34(-17.145,-5.715) K35(-18.415,-5.715) K36(-19.685,-5.715) K37(-20.955,-5.715) K38(-22.225,-5.715) K39(-23.495,-5.715) K40(-24.765,-5.715) L1(24.765,-6.985) L2(23.495,-6.985) L3(22.225,-6.985) L4(20.955,-6.985) L5(19.685,-6.985) L6(18.415,-6.985) L7(17.145,-6.985) L8(15.875,-6.985) L9(14.605,-6.985) L10(13.335,-6.985) L11(12.065,-6.985) L12(10.795,-6.985) L13(9.525,-6.985) L14(8.255,-6.985) L15(6.985,-6.985) L16(5.715,-6.985) L17(4.445,-6.985) L18(3.175,-6.985) L19(1.905,-6.985) L20(0.635,-6.985) L21(-0.635,-6.985) L22(-1.905,-6.985) L23(-3.175,-6.985) L24(-4.445,-6.985) L25(-5.715,-6.985) L26(-6.985,-6.985) L27(-8.255,-6.985) L28(-9.525,-6.985) L29(-10.795,-6.985) L30(-12.065,-6.985) L31(-13.335,-6.985) L32(-14.605,-6.985) L33(-15.875,-6.985) L34(-17.145,-6.985) L35(-18.415,-6.985) L36(-19.685,-6.985) L37(-20.955,-6.985) L38(-22.225,-6.985) L39(-23.495,-6.985) L40(-24.765,-6.985) M1(24.765,-8.255) M2(23.495,-8.255) M3(22.225,-8.255) M4(20.955,-8.255) M5(19.685,-8.255) M6(18.415,-8.255) M7(17.145,-8.255) M8(15.875,-8.255) M9(14.605,-8.255) M10(13.335,-8.255) M11(12.065,-8.255) M12(10.795,-8.255) M13(9.525,-8.255) M14(8.255,-8.255) M15(6.985,-8.255) M16(5.715,-8.255) M17(4.445,-8.255) M18(3.175,-8.255) M19(1.905,-8.255) M20(0.635,-8.255) M21(-0.635,-8.255) M22(-1.905,-8.255) M23(-3.175,-8.255) M24(-4.445,-8.255) M25(-5.715,-8.255) M26(-6.985,-8.255) M27(-8.255,-8.255) M28(-9.525,-8.255) M29(-10.795,-8.255) M30(-12.065,-8.255) M31(-13.335,-8.255) M32(-14.605,-8.255) M33(-15.875,-8.255) M34(-17.145,-8.255) M35(-18.415,-8.255) M36(-19.685,-8.255) M37(-20.955,-8.255) M38(-22.225,-8.255) M39(-23.495,-8.255) M40(-24.765,-8.255) Y1(24.765,8.255) Y2(23.495,8.255) Y3(22.225,8.255) Y4(20.955,8.255) Y5(19.685,8.255) Y6(18.415,8.255) Y7(17.145,8.255) Y8(15.875,8.255) Y9(14.605,8.255) Y10(13.335,8.255) Y11(12.065,8.255) Y12(10.795,8.255) Y13(9.525,8.255) Y14(8.255,8.255) Y15(6.985,8.255) Y16(5.715,8.255) Y17(4.445,8.255) Y18(3.175,8.255) Y19(1.905,8.255) Y20(0.635,8.255) Y21(-0.635,8.255) Y22(-1.905,8.255) Y23(-3.175,8.255) Y24(-4.445,8.255) Y25(-5.715,8.255) Y26(-6.985,8.255) Y27(-8.255,8.255) Y28(-9.525,8.255) Y29(-10.795,8.255) Y30(-12.065,8.255) Y31(-13.335,8.255) Y32(-14.605,8.255) Y33(-15.875,8.255) Y34(-17.145,8.255) Y35(-18.415,8.255) Y36(-19.685,8.255) Y37(-20.955,8.255) Y38(-22.225,8.255) Y39(-23.495,8.255) Y40(-24.765,8.255) Z1(24.765,6.985) Z2(23.495,6.985) Z3(22.225,6.985) Z4(20.955,6.985) Z5(19.685,6.985) Z6(18.415,6.985) Z7(17.145,6.985) Z8(15.875,6.985) Z9(14.605,6.985) Z10(13.335,6.985) Z11(12.065,6.985) Z12(10.795,6.985) Z13(9.525,6.985) Z14(8.255,6.985) Z15(6.985,6.985) Z16(5.715,6.985) Z17(4.445,6.985) Z18(3.175,6.985) Z19(1.905,6.985) Z20(0.635,6.985) Z21(-0.635,6.985) Z22(-1.905,6.985) Z23(-3.175,6.985) Z24(-4.445,6.985) Z25(-5.715,6.985) Z26(-6.985,6.985) Z27(-8.255,6.985) Z28(-9.525,6.985) Z29(-10.795,6.985) Z30(-12.065,6.985) Z31(-13.335,6.985) Z32(-14.605,6.985) Z33(-15.875,6.985) Z34(-17.145,6.985) Z35(-18.415,6.985) Z36(-19.685,6.985) Z37(-20.955,6.985) Z38(-22.225,6.985) Z39(-23.495,6.985) Z40(-24.765,6.985)
